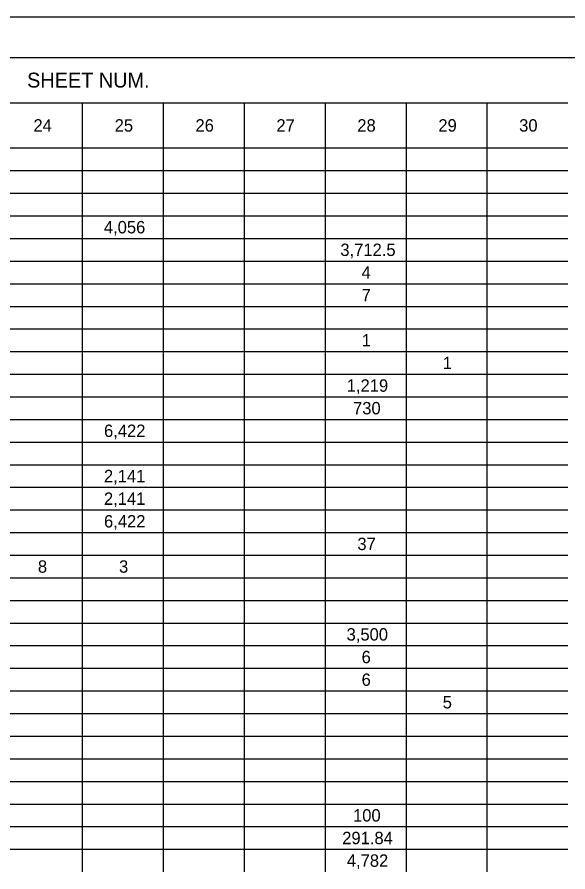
# Model space of a CAD drawing. Extents: x 0 to 34, y 0 to 22.
# Drawn here: x 6.71 to 13.53, y 11.42 to 22 of the extents above; entities that cross this region are included whole.
import ezdxf

# ---------------------------------------------------------------- set-up
doc = ezdxf.new("R2010")
doc.units = 0
for name, color, linetype in [('SH_Border', 7, 'Continuous'), ('SH_Cut_Line', 7, 'Continuous'), ('SH_Text', 7, 'Continuous')]:
    doc.layers.add(name, color=color, linetype=linetype)

msp = doc.modelspace()

# ---------------------------------------------------------------- linework, layer by layer
at = {"layer": 'SH_Border'}
msp.add_lwpolyline([(1.5, 21.5), (33.5, 21.5), (33.5, 0.5), (1.5, 0.5)], close=True, dxfattribs=at)
at = {"layer": 'SH_Cut_Line'}
msp.add_lwpolyline([(0, 0), (34, 0), (34, 22), (0, 22)], close=True, dxfattribs=at)
at = {"layer": 'SH_Text'}
for p, q in [((6.513, 21.5), (7.516, 21.5)), ((7.516, 21.5), (12.529, 21.5)), ((12.529, 21.5), (13.532, 21.5)), ((6.513, 20.94), (7.516, 20.94)), ((7.516, 20.94), (12.529, 20.94)), ((7.516, 20.94), (7.516, 20.66)), ((8.519, 20.94), (8.519, 20.66)), ((9.521, 20.94), (9.521, 20.66)), ((10.524, 20.94), (10.524, 20.66)), ((11.527, 20.94), (11.527, 20.66)), ((12.529, 20.94), (13.532, 20.94)), ((12.529, 20.94), (12.529, 20.66)), ((7.516, 20.66), (7.516, 20.38)), ((8.519, 20.66), (8.519, 20.38)), ((9.521, 20.66), (9.521, 20.38)), ((10.524, 20.66), (10.524, 20.38)), ((11.527, 20.66), (11.527, 20.38)), ((12.529, 20.66), (12.529, 20.38)), ((6.513, 20.38), (7.516, 20.38)), ((7.516, 20.38), (12.529, 20.38)), ((7.516, 20.38), (7.516, 20.1)), ((8.519, 20.38), (8.519, 20.1)), ((9.521, 20.38), (9.521, 20.1)), ((10.524, 20.38), (10.524, 20.1)), ((11.527, 20.38), (11.527, 20.1)), ((12.529, 20.38), (13.532, 20.38)), ((12.529, 20.38), (12.529, 20.1)), ((6.513, 20.1), (7.516, 20.1)), ((7.516, 20.1), (12.529, 20.1)), ((7.516, 20.1), (7.516, 18.7)), ((8.519, 20.1), (8.519, 18.7)), ((9.521, 20.1), (9.521, 18.7)), ((10.524, 20.1), (10.524, 18.7)), ((11.527, 20.1), (11.527, 18.7)), ((12.529, 20.1), (13.532, 20.1)), ((12.529, 20.1), (12.529, 18.7)), ((6.513, 19.82), (7.516, 19.82)), ((7.516, 19.82), (12.529, 19.82)), ((12.529, 19.82), (13.532, 19.82)), ((6.513, 19.54), (7.516, 19.54)), ((7.516, 19.54), (12.529, 19.54)), ((12.529, 19.54), (13.532, 19.54)), ((6.513, 19.26), (7.516, 19.26)), ((7.516, 19.26), (12.529, 19.26)), ((12.529, 19.26), (13.532, 19.26)), ((6.513, 18.98), (7.516, 18.98)), ((7.516, 18.98), (12.529, 18.98)), ((12.529, 18.98), (13.532, 18.98)), ((6.513, 18.7), (7.516, 18.7)), ((7.516, 18.7), (12.529, 18.7)), ((7.516, 18.7), (7.516, 18.14)), ((8.519, 18.7), (8.519, 18.14)), ((9.521, 18.7), (9.521, 18.14)), ((10.524, 18.7), (10.524, 18.14)), ((11.527, 18.7), (11.527, 18.14)), ((12.529, 18.7), (13.532, 18.7)), ((12.529, 18.7), (12.529, 18.14)), ((6.513, 18.42), (7.516, 18.42)), ((7.516, 18.42), (12.529, 18.42)), ((12.529, 18.42), (13.532, 18.42)), ((6.513, 18.14), (7.516, 18.14)), ((7.516, 18.14), (12.529, 18.14)), ((7.516, 18.14), (7.516, 17.86)), ((8.519, 18.14), (8.519, 17.86)), ((9.521, 18.14), (9.521, 17.86)), ((10.524, 18.14), (10.524, 17.86)), ((11.527, 18.14), (11.527, 17.86)), ((12.529, 18.14), (13.532, 18.14)), ((12.529, 18.14), (12.529, 17.86)), ((6.513, 17.86), (7.516, 17.86)), ((7.516, 17.86), (12.529, 17.86)), ((7.516, 17.86), (7.516, 17.58)), ((8.519, 17.86), (8.519, 17.58)), ((9.521, 17.86), (9.521, 17.58)), ((10.524, 17.86), (10.524, 17.58)), ((11.527, 17.86), (11.527, 17.58)), ((12.529, 17.86), (13.532, 17.86)), ((12.529, 17.86), (12.529, 17.58)), ((6.513, 17.58), (7.516, 17.58)), ((7.516, 17.58), (12.529, 17.58)), ((7.516, 17.58), (7.516, 17.3)), ((8.519, 17.58), (8.519, 17.3)), ((9.521, 17.58), (9.521, 17.3)), ((10.524, 17.58), (10.524, 17.3)), ((11.527, 17.58), (11.527, 17.3)), ((12.529, 17.58), (13.532, 17.58)), ((12.529, 17.58), (12.529, 17.3)), ((6.513, 17.3), (7.516, 17.3)), ((7.516, 17.3), (12.529, 17.3)), ((7.516, 17.3), (7.516, 17.02)), ((8.519, 17.3), (8.519, 17.02)), ((9.521, 17.3), (9.521, 17.02)), ((10.524, 17.3), (10.524, 17.02)), ((11.527, 17.3), (11.527, 17.02)), ((12.529, 17.3), (13.532, 17.3)), ((12.529, 17.3), (12.529, 17.02)), ((6.513, 17.02), (7.516, 17.02)), ((7.516, 17.02), (12.529, 17.02)), ((7.516, 17.02), (7.516, 16.74)), ((8.519, 17.02), (8.519, 16.74)), ((9.521, 17.02), (9.521, 16.74)), ((10.524, 17.02), (10.524, 16.74)), ((11.527, 17.02), (11.527, 16.74)), ((12.529, 17.02), (13.532, 17.02)), ((12.529, 17.02), (12.529, 16.74)), ((6.513, 16.74), (7.516, 16.74)), ((7.516, 16.74), (12.529, 16.74)), ((7.516, 16.74), (7.516, 16.18)), ((8.519, 16.74), (8.519, 16.18)), ((9.521, 16.74), (9.521, 16.18)), ((10.524, 16.74), (10.524, 16.18)), ((11.527, 16.74), (11.527, 16.18)), ((12.529, 16.74), (13.532, 16.74)), ((12.529, 16.74), (12.529, 16.18)), ((6.513, 16.46), (7.516, 16.46)), ((7.516, 16.46), (12.529, 16.46)), ((12.529, 16.46), (13.532, 16.46)), ((6.513, 16.18), (7.516, 16.18)), ((7.516, 16.18), (12.529, 16.18)), ((7.516, 16.18), (7.516, 15.9)), ((8.519, 16.18), (8.519, 15.9)), ((9.521, 16.18), (9.521, 15.9)), ((10.524, 16.18), (10.524, 15.9)), ((11.527, 16.18), (11.527, 15.9)), ((12.529, 16.18), (13.532, 16.18)), ((12.529, 16.18), (12.529, 15.9)), ((6.513, 15.9), (7.516, 15.9)), ((7.516, 15.9), (12.529, 15.9)), ((7.516, 15.9), (7.516, 15.62)), ((8.519, 15.9), (8.519, 15.62)), ((9.521, 15.9), (9.521, 15.62)), ((10.524, 15.9), (10.524, 15.62)), ((11.527, 15.9), (11.527, 15.62)), ((12.529, 15.9), (13.532, 15.9)), ((12.529, 15.9), (12.529, 15.62)), ((6.513, 15.62), (7.516, 15.62)), ((7.516, 15.62), (12.529, 15.62)), ((7.516, 15.62), (7.516, 15.34)), ((8.519, 15.62), (8.519, 15.34)), ((9.521, 15.62), (9.521, 15.34)), ((10.524, 15.62), (10.524, 15.34)), ((11.527, 15.62), (11.527, 15.34)), ((12.529, 15.62), (13.532, 15.62)), ((12.529, 15.62), (12.529, 15.34)), ((6.513, 15.34), (7.516, 15.34)), ((7.516, 15.34), (12.529, 15.34)), ((7.516, 15.34), (7.516, 14.78)), ((8.519, 15.34), (8.519, 14.78)), ((9.521, 15.34), (9.521, 14.78)), ((10.524, 15.34), (10.524, 14.78)), ((11.527, 15.34), (11.527, 14.78)), ((12.529, 15.34), (13.532, 15.34)), ((12.529, 15.34), (12.529, 14.78)), ((6.513, 15.06), (7.516, 15.06)), ((7.516, 15.06), (12.529, 15.06)), ((12.529, 15.06), (13.532, 15.06)), ((6.513, 14.78), (7.516, 14.78)), ((7.516, 14.78), (12.529, 14.78)), ((7.516, 14.78), (7.516, 14.5)), ((8.519, 14.78), (8.519, 14.5)), ((9.521, 14.78), (9.521, 14.5)), ((10.524, 14.78), (10.524, 14.5)), ((11.527, 14.78), (11.527, 14.5)), ((12.529, 14.78), (13.532, 14.78)), ((12.529, 14.78), (12.529, 14.5)), ((6.513, 14.5), (7.516, 14.5)), ((7.516, 14.5), (12.529, 14.5)), ((7.516, 14.5), (7.516, 14.22)), ((8.519, 14.5), (8.519, 14.22)), ((9.521, 14.5), (9.521, 14.22)), ((10.524, 14.5), (10.524, 14.22)), ((11.527, 14.5), (11.527, 14.22)), ((12.529, 14.5), (13.532, 14.5)), ((12.529, 14.5), (12.529, 14.22)), ((6.513, 14.22), (7.516, 14.22)), ((7.516, 14.22), (12.529, 14.22)), ((7.516, 14.22), (7.516, 13.94)), ((8.519, 14.22), (8.519, 13.94)), ((9.521, 14.22), (9.521, 13.94)), ((10.524, 14.22), (10.524, 13.94)), ((11.527, 14.22), (11.527, 13.94)), ((12.529, 14.22), (13.532, 14.22)), ((12.529, 14.22), (12.529, 13.94)), ((6.513, 13.94), (7.516, 13.94)), ((7.516, 13.94), (12.529, 13.94)), ((7.516, 13.94), (7.516, 11.7)), ((8.519, 13.94), (8.519, 11.7)), ((9.521, 13.94), (9.521, 11.7)), ((10.524, 13.94), (10.524, 11.7)), ((11.527, 13.94), (11.527, 11.7)), ((12.529, 13.94), (13.532, 13.94)), ((12.529, 13.94), (12.529, 11.7)), ((6.513, 13.66), (7.516, 13.66)), ((7.516, 13.66), (12.529, 13.66)), ((12.529, 13.66), (13.532, 13.66)), ((6.513, 13.38), (7.516, 13.38)), ((7.516, 13.38), (12.529, 13.38)), ((12.529, 13.38), (13.532, 13.38)), ((6.513, 13.1), (7.516, 13.1)), ((7.516, 13.1), (12.529, 13.1)), ((12.529, 13.1), (13.532, 13.1)), ((6.513, 12.82), (7.516, 12.82)), ((7.516, 12.82), (12.529, 12.82)), ((12.529, 12.82), (13.532, 12.82)), ((6.513, 12.54), (7.516, 12.54)), ((7.516, 12.54), (12.529, 12.54)), ((12.529, 12.54), (13.532, 12.54)), ((6.513, 12.26), (7.516, 12.26)), ((7.516, 12.26), (12.529, 12.26)), ((12.529, 12.26), (13.532, 12.26)), ((6.513, 11.98), (7.516, 11.98)), ((7.516, 11.98), (12.529, 11.98)), ((12.529, 11.98), (13.532, 11.98)), ((6.513, 11.7), (7.516, 11.7)), ((7.516, 11.7), (12.529, 11.7)), ((7.516, 11.7), (7.516, 11.42)), ((8.519, 11.7), (8.519, 11.42)), ((9.521, 11.7), (9.521, 11.42)), ((10.524, 11.7), (10.524, 11.42)), ((11.527, 11.7), (11.527, 11.42)), ((12.529, 11.7), (13.532, 11.7)), ((12.529, 11.7), (12.529, 11.42))]:
    msp.add_line(p, q, dxfattribs=at)

# ---------------------------------------------------------------- texts
for s, height, p in [('SHEET NUM.', 0.184, (6.832, 21.128)), ('24', 0.1533, (6.911, 20.583)), ('25', 0.1533, (7.917, 20.583)), ('26', 0.1533, (8.918, 20.583)), ('27', 0.1533, (9.921, 20.583)), ('28', 0.1533, (10.923, 20.583)), ('29', 0.1533, (11.927, 20.583)), ('30', 0.1533, (12.928, 20.583)), ('4,056', 0.1533, (7.783, 19.323)), ('3,712.5', 0.1533, (10.713, 19.043)), ('4', 0.153, (10.975, 18.763)), ('7', 0.153, (10.977, 18.483)), ('1', 0.153, (10.978, 17.923)), ('1', 0.153, (11.981, 17.643)), ('1,219', 0.1533, (10.792, 17.363)), ('730', 0.1533, (10.87, 17.083)), ('6,422', 0.1533, (7.785, 16.803)), ('2,141', 0.1533, (7.784, 16.243)), ('2,141', 0.1533, (7.784, 15.963)), ('6,422', 0.1533, (7.785, 15.683)), ('37', 0.1533, (10.924, 15.403)), ('8', 0.153, (6.966, 15.123)), ('3', 0.153, (7.971, 15.123)), ('3,500', 0.1533, (10.79, 14.283)), ('6', 0.153, (10.976, 14.003)), ('6', 0.153, (10.976, 13.723)), ('5', 0.153, (11.981, 13.443)), ('100', 0.1533, (10.87, 12.043)), ('291.84', 0.1533, (10.736, 11.763)), ('4,782', 0.1533, (10.793, 11.483))]:
    msp.add_text(s, height=height, dxfattribs=at).set_placement(p)

doc.saveas('drawing.dxf')
